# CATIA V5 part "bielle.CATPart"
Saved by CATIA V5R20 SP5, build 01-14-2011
Part number: bielle
Bounding box of the stored display mesh (mm): x -16 to 16, y -6 to 46, z -16 to -4
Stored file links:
  F:\Catia_finish\bielle.CATPart
  F:\Catia_finish\ASS_compresseur.CATProduct
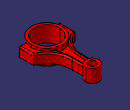
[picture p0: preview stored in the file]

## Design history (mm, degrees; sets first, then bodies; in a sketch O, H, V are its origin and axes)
External parameters (linked from other documents)
  External.longueur_bielle = 35 mm
Set1
  Point1: linked copy from another document
  Line1: linked copy from another document
  Point2: linked copy from another document
Body1 (main body)
  Sketch1 on xy-plane, origin (0, 0, 0), H (1, 0, 0), V (0, 1, 0)
    circle A1 centre (0, 6) radius 12
    point P1 (0, 6)
    reference projected point E1 (0, 6) from Point1
    radius A1 = 12
    coincidence: E1 P1
  Pad1: profile Sketch1, direction (0, 0, 1), length -4, opposite side length 10
  Sketch2 on xy-plane, origin (0, 0, 0), H (1, 0, 0), V (0, 1, 0)
    circle A1 centre (0, 41) radius 5
    point P1 (0, 41)
    reference projected point E1 (0, 41) from Point2
    radius A1 = 5
    coincidence: P1 E1
  Pad2: profile Sketch2, direction (0, 0, 1), length -5, opposite side length 10
  Shell1: ExtOffset 0, Face (end face of Pad1; start face of Pad2; start face of Pad1; end face of Pad2), IntOffset 2
  Body2
    Sketch3 on xy-plane, origin (0, 0, 0), H (1, 0, 0), V (0, 1, 0)
      line L1 (-16, 11.6667) -> (-16, 0)
      line L2 (-16, 0) -> (0, 0)
      point P3 (0, 0)
      line L3 (0, 0) -> (0, 41)
      line L4 (0, 41) -> (-4, 41)
      line L5 (-4, 41) -> (-4, 29.3333)
      arc A1 centre (-23.0046, 29.3333) radius 19.0046 from (-4, 29.3333) to (-16, 11.6667) cw
      reference projected point E1 (0, 6) from Point1
      length L3 = 41 {= External.longueur_bielle +6mm}
      distance L2 E1 = 6
      length L2 = 16
      length L1 = 11.6667 {= External.longueur_bielle /3}
      length L5 = 11.6667 {= External.longueur_bielle /3}
      length L4 = 4
      vertical: L1 V, L3 V, L5 V
      coincidence: P3 V
      horizontal: L2 H, L4 H
      tangency: A1 L5
    Pad3: profile Sketch3, direction (0, 0, 1), length -6, opposite side length 10
    Sketch4 on end face of Pad3, origin (0, 0, -6), H (1, 0, 0), V (0, 1, 0)
      line L1 (-2.5, 29.2033) -> (-2.5, 41)
      line L2 (-2.5, 41) -> (0, 41)
      point P3 (0, 41)
      line L3 (0, 41) -> (0, 9.5)
      line L4 (0, 9.5) -> (-11.4782, 9.5)
      point P5 (-11.4782, 9.5)
      arc A1 centre (-28.6093, 29.2033) radius 26.1093 from (-11.4782, 9.5) to (-2.5, 29.2033) ccw
      reference projected circle E1 centre (0, 6) radius 12 from edge [face of Pad1 from Sketch1.A1 | end face of Pad1]
      reference projected point E2 (0, 41) from Line1
      distance L1 L3 = 2.5
      distance L2 L4 = 31.5 {= External.longueur_bielle *0.9}
      vertical: L1 V, L3 V
      coincidence: P3 V, P5 E1, P3 E2
      horizontal: L2 H, L4 H
      tangency: A1 L1
    Pocket1: profile Sketch4, direction (0, 0, -1), length 2
  Trim1: tool Body2
  Mirror1: of the body so far, about face of Pad3 from Sketch3.L3
  Fillet1: radius 1, on edge [face of Mirror1 | face of Mirror1] (x3); edge [face of Pad3 from Sketch3.L1 | end face of Pad3]; edge [face of Pad3 from Sketch3.A1 | end face of Pad3]; edge [face of Pad3 from Sketch3.L5 | end face of Pad3]
  Fillet2: radius 1, on edge [face of Pocket1 from Sketch4.A1 | face of Mirror1], deactivated
  Fillet3: radius 1, on edge [face of Mirror1 | face of Mirror1]
  Fillet4: radius 1, on edge [face of Mirror1 | face of Mirror1] (x2); edge [face of Mirror1 | face of Fillet1]
  Fillet5: radius 1, on edge [face of Pad3 from Sketch3.L2 | end face of Pad3]; edge [face of Pad3 from Sketch3.L2 | face of Fillet1]; edge [face of Pad3 from Sketch3.L2 | face of Pad3 from Sketch3.L1]
  Mirror2: of the body so far, about face of Pad1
